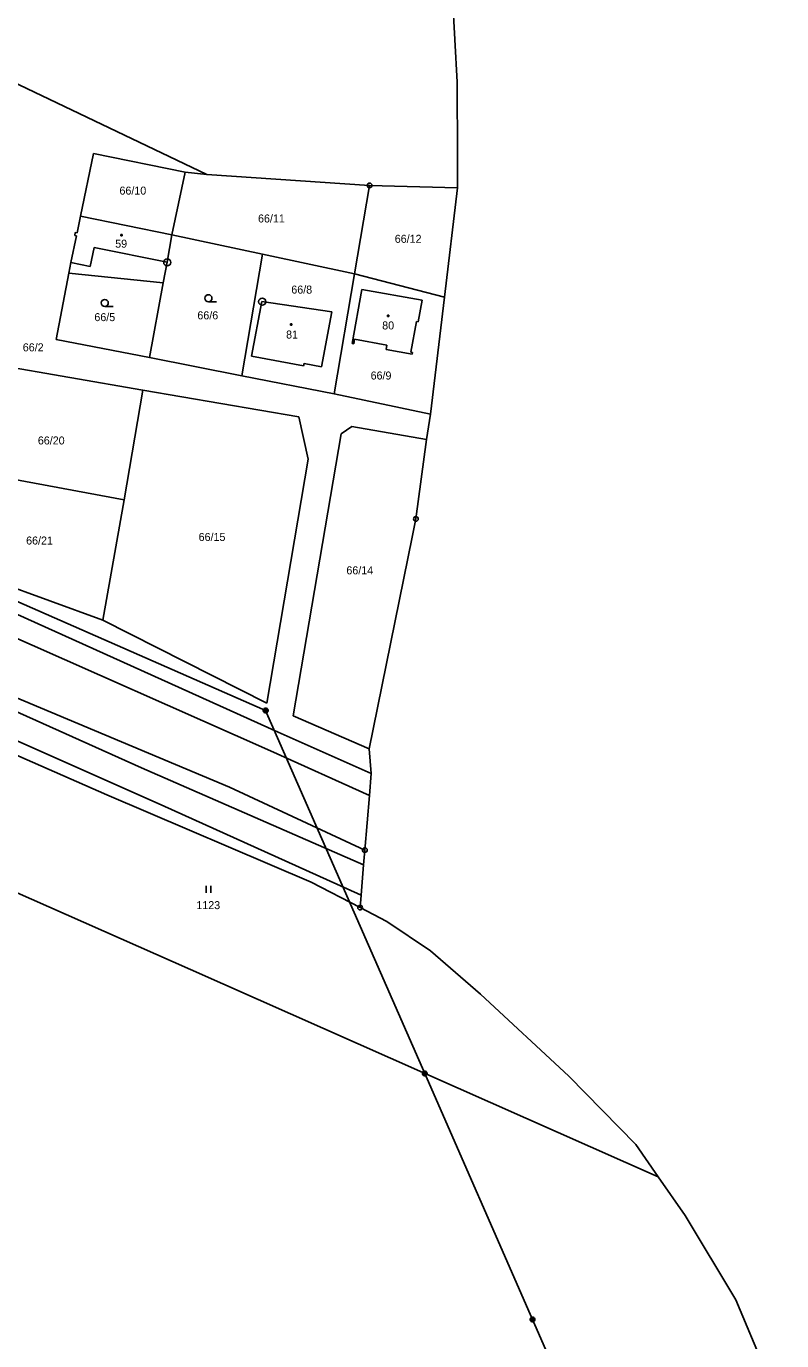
# Model space of a CAD drawing. Extents: x -796130 to -793145, y -1109506 to -1106267.
# Drawn here: x -794147 to -793986.5, y -1108157.6 to -1107878.4 of the extents above; entities that cross this region are included whole.
import ezdxf

# ---------------------------------------------------------------- set-up
doc = ezdxf.new("R2010")
doc.units = 0
for name, color, linetype in [('Vrstva 1', 7, 'Continuous'), ('Vrstva 12', 7, 'Continuous'), ('Vrstva 14', 7, 'Continuous'), ('Vrstva 15', 7, 'Continuous'), ('Vrstva 2', 7, 'Continuous'), ('Vrstva 23', 7, 'Continuous'), ('Vrstva 25', 7, 'Continuous'), ('Vrstva 26', 7, 'Continuous'), ('Vrstva 28', 7, 'Continuous'), ('Vrstva 4', 7, 'Continuous')]:
    doc.layers.add(name, color=color, linetype=linetype)

msp = doc.modelspace()

# ---------------------------------------------------------------- linework, layer by layer
at = {"layer": 'Vrstva 1'}
for p, q in [((-794175.87, -1107877.74), (-794108.67, -1107909.82)), ((-794132.74, -1107905.36), (-794135.47, -1107918.72)), ((-794113.29, -1107909.33), (-794132.74, -1107905.36)), ((-794116.06, -1107922.68), (-794113.29, -1107909.33)), ((-794108.67, -1107909.82), (-794113.29, -1107909.33)), ((-794108.67, -1107909.82), (-794074.07, -1107912.16)), ((-794077.27, -1107930.93), (-794074.07, -1107912.16)), ((-794074.07, -1107912.16), (-794055.42, -1107912.68)), ((-794136.2, -1107922.24), (-794135.47, -1107918.72)), ((-794135.47, -1107918.72), (-794116.06, -1107922.68)), ((-794137.52, -1107928.56), (-794136.34, -1107922.88)), ((-794136.73, -1107922.8), (-794136.63, -1107922.15)), ((-794136.34, -1107922.88), (-794136.73, -1107922.8)), ((-794136.63, -1107922.15), (-794136.2, -1107922.24)), ((-794116.06, -1107922.68), (-794117.11, -1107928.47)), ((-794116.06, -1107922.68), (-794096.83, -1107926.75)), ((-794137.96, -1107930.82), (-794137.52, -1107928.56)), ((-794117.11, -1107928.47), (-794117.92, -1107932.88)), ((-794096.83, -1107926.75), (-794101.21, -1107952.61)), ((-794077.27, -1107930.93), (-794096.83, -1107926.75)), ((-794140.69, -1107944.88), (-794137.96, -1107930.82)), ((-794117.92, -1107932.88), (-794137.96, -1107930.82)), ((-794077.27, -1107930.93), (-794081.59, -1107956.43)), ((-794077.27, -1107930.93), (-794058.17, -1107935.92)), ((-794117.92, -1107932.88), (-794120.84, -1107948.74)), ((-794077.81, -1107945.74), (-794075.75, -1107934.3)), ((-794075.75, -1107934.3), (-794062.94, -1107936.55)), ((-794099.19, -1107948.43), (-794097, -1107936.82)), ((-794097, -1107936.82), (-794082.08, -1107939.06)), ((-794062.94, -1107936.55), (-794063.78, -1107941.17)), ((-794082.08, -1107939.06), (-794084.29, -1107950.7)), ((-794064.14, -1107941.1), (-794065.34, -1107947.62)), ((-794063.78, -1107941.17), (-794064.14, -1107941.1)), ((-794140.69, -1107944.88), (-794120.84, -1107948.74)), ((-794077.46, -1107945.8), (-794077.81, -1107945.74)), ((-794077.28, -1107944.84), (-794077.46, -1107945.8)), ((-794070.42, -1107946.08), (-794077.28, -1107944.84)), ((-794088.14, -1107950.51), (-794099.19, -1107948.43)), ((-794070.59, -1107947.04), (-794070.42, -1107946.08)), ((-794065.02, -1107948.04), (-794070.59, -1107947.04)), ((-794065.34, -1107947.62), (-794064.96, -1107947.69)), ((-794064.96, -1107947.69), (-794065.02, -1107948.04)), ((-794153.9, -1107950.19), (-794122.25, -1107955.65)), ((-794120.84, -1107948.74), (-794101.21, -1107952.61)), ((-794088, -1107949.99), (-794088.14, -1107950.51)), ((-794084.29, -1107950.7), (-794088, -1107949.99)), ((-794101.21, -1107952.61), (-794081.59, -1107956.43)), ((-794122.25, -1107955.65), (-794126.24, -1107978.94)), ((-794122.25, -1107955.65), (-794089.09, -1107961.35)), ((-794081.59, -1107956.43), (-794061.11, -1107960.74)), ((-794089.09, -1107961.35), (-794087.14, -1107970.33)), ((-794090.35, -1108024.9), (-794080.1, -1107964.97)), ((-794080.1, -1107964.97), (-794077.82, -1107963.41)), ((-794077.82, -1107963.41), (-794061.96, -1107966.12)), ((-794087.14, -1107970.33), (-794095.89, -1108022.19)), ((-794158.08, -1107973.04), (-794126.24, -1107978.94)), ((-794126.24, -1107978.94), (-794130.79, -1108004.55)), ((-794130.79, -1108004.55), (-794161.9, -1107993.23)), ((-794168.15, -1107994.62), (-794093.53, -1108028.31)), ((-794169.94, -1107999.17), (-794095.11, -1108032.28)), ((-794095.89, -1108022.19), (-794130.79, -1108004.55)), ((-794158.82, -1108016.94), (-794103.82, -1108039.99)), ((-794129.88, -1108041.67), (-794165.82, -1108025.89)), ((-794074.16, -1108031.9), (-794090.35, -1108024.9)), ((-794093.53, -1108028.31), (-794073.75, -1108037.09)), ((-794095.11, -1108032.28), (-794074.13, -1108041.77)), ((-794103.82, -1108039.99), (-794075.09, -1108053.38)), ((-794196.39, -1108041.5), (-794112.13, -1108078.79)), ((-794086.5, -1108060.2), (-794129.88, -1108041.67)), ((-794076.1, -1108065.62), (-794086.5, -1108060.2)), ((-794112.13, -1108078.79), (-794012.75, -1108122.82))]:
    msp.add_line(p, q, dxfattribs=at)
at = {"layer": 'Vrstva 12'}
for p, q in [((-794096.16, -1108023.73), (-794162.66, -1107994.6)), ((-794062.37, -1108100.85), (-794096.16, -1108023.73)), ((-794039.45, -1108153.13), (-794062.37, -1108100.85)), ((-794018.04, -1108201.97), (-794039.45, -1108153.13))]:
    msp.add_line(p, q, dxfattribs=at)
at = {"layer": 'Vrstva 2'}
for p, q in [((-794132.62, -1107925.33), (-794133.44, -1107929.39)), ((-794117.11, -1107928.47), (-794132.62, -1107925.33)), ((-794133.44, -1107929.39), (-794137.52, -1107928.56)), ((-794122.52, -1108035.9), (-794180.45, -1108009.94)), ((-794181.93, -1108015.5), (-794118.39, -1108043.8)), ((-794075.35, -1108056.55), (-794122.52, -1108035.9)), ((-794118.39, -1108043.8), (-794075.88, -1108062.99))]:
    msp.add_line(p, q, dxfattribs=at)
at = {"layer": 'Vrstva 23'}
for p, q in [((-794108.32, -1107936.89), (-794106.57, -1107936.89)), ((-794130.34, -1107937.89), (-794128.59, -1107937.89)), ((-794108.81, -1108062.51), (-794108.81, -1108061.01)), ((-794107.81, -1108061.01), (-794107.81, -1108062.51))]:
    msp.add_line(p, q, dxfattribs=at)
for centre in [(-794130.34, -1107937.14), (-794108.32, -1107936.14)]:
    msp.add_circle(centre, 0.75, dxfattribs=at)
at = {"layer": 'Vrstva 25'}
for p, q in [((-794126.92, -1107922.61), (-794126.62, -1107922.61)), ((-794126.92, -1107922.91), (-794126.92, -1107922.61)), ((-794126.62, -1107922.91), (-794126.92, -1107922.91)), ((-794126.62, -1107922.61), (-794126.62, -1107922.91)), ((-794070.29, -1107939.74), (-794069.99, -1107939.74)), ((-794070.29, -1107940.04), (-794070.29, -1107939.74)), ((-794069.99, -1107940.04), (-794070.29, -1107940.04)), ((-794069.99, -1107939.74), (-794069.99, -1107940.04)), ((-794090.89, -1107941.56), (-794090.59, -1107941.56)), ((-794090.89, -1107941.86), (-794090.89, -1107941.56)), ((-794090.59, -1107941.86), (-794090.89, -1107941.86)), ((-794090.59, -1107941.56), (-794090.59, -1107941.86))]:
    msp.add_line(p, q, dxfattribs=at)
at = {"layer": 'Vrstva 26'}
for p, q in [((-794096.66, -1108023.63), (-794096.56, -1108023.43)), ((-794096.66, -1108023.83), (-794096.66, -1108023.63)), ((-794096.56, -1108024.03), (-794096.66, -1108023.83)), ((-794096.56, -1108023.43), (-794096.46, -1108023.33)), ((-794096.46, -1108024.13), (-794096.56, -1108024.03)), ((-794096.46, -1108023.33), (-794096.26, -1108023.23)), ((-794096.46, -1108023.53), (-794096.46, -1108023.93)), ((-794096.46, -1108023.93), (-794096.26, -1108024.03)), ((-794096.26, -1108024.23), (-794096.46, -1108024.13)), ((-794096.26, -1108023.23), (-794096.06, -1108023.23)), ((-794096.26, -1108024.03), (-794096.26, -1108023.43)), ((-794096.26, -1108023.43), (-794096.06, -1108023.43)), ((-794096.06, -1108023.23), (-794095.86, -1108023.33)), ((-794096.06, -1108023.43), (-794096.06, -1108024.03)), ((-794096.06, -1108024.03), (-794095.86, -1108023.93)), ((-794095.86, -1108024.13), (-794096.06, -1108024.23)), ((-794095.86, -1108023.33), (-794095.76, -1108023.43)), ((-794095.86, -1108023.93), (-794095.86, -1108023.53)), ((-794095.76, -1108024.03), (-794095.86, -1108024.13)), ((-794095.76, -1108023.43), (-794095.66, -1108023.63)), ((-794095.66, -1108023.83), (-794095.76, -1108024.03)), ((-794095.66, -1108023.63), (-794095.66, -1108023.83)), ((-794096.06, -1108024.23), (-794096.26, -1108024.23)), ((-794062.87, -1108100.75), (-794062.77, -1108100.55)), ((-794062.87, -1108100.95), (-794062.87, -1108100.75)), ((-794062.77, -1108101.15), (-794062.87, -1108100.95)), ((-794062.77, -1108100.55), (-794062.67, -1108100.45)), ((-794062.67, -1108101.25), (-794062.77, -1108101.15)), ((-794062.67, -1108100.45), (-794062.47, -1108100.35)), ((-794062.67, -1108100.65), (-794062.67, -1108101.05)), ((-794062.67, -1108101.05), (-794062.47, -1108101.15)), ((-794062.47, -1108101.35), (-794062.67, -1108101.25)), ((-794062.47, -1108100.35), (-794062.27, -1108100.35)), ((-794062.47, -1108101.15), (-794062.47, -1108100.55)), ((-794062.47, -1108100.55), (-794062.27, -1108100.55)), ((-794062.27, -1108101.35), (-794062.47, -1108101.35)), ((-794062.27, -1108100.35), (-794062.07, -1108100.45)), ((-794062.27, -1108100.55), (-794062.27, -1108101.15)), ((-794062.27, -1108101.15), (-794062.07, -1108101.05)), ((-794062.07, -1108101.25), (-794062.27, -1108101.35)), ((-794062.07, -1108100.45), (-794061.97, -1108100.55)), ((-794062.07, -1108101.05), (-794062.07, -1108100.65)), ((-794061.97, -1108101.15), (-794062.07, -1108101.25)), ((-794061.97, -1108100.55), (-794061.87, -1108100.75)), ((-794061.87, -1108100.95), (-794061.97, -1108101.15)), ((-794061.87, -1108100.75), (-794061.87, -1108100.95)), ((-794039.95, -1108153.03), (-794039.85, -1108152.83)), ((-794039.95, -1108153.23), (-794039.95, -1108153.03)), ((-794039.85, -1108153.43), (-794039.95, -1108153.23)), ((-794039.85, -1108152.83), (-794039.75, -1108152.73)), ((-794039.75, -1108153.53), (-794039.85, -1108153.43)), ((-794039.75, -1108152.73), (-794039.55, -1108152.63)), ((-794039.75, -1108152.93), (-794039.75, -1108153.33)), ((-794039.75, -1108153.33), (-794039.55, -1108153.43)), ((-794039.55, -1108153.63), (-794039.75, -1108153.53)), ((-794039.55, -1108152.63), (-794039.35, -1108152.63)), ((-794039.55, -1108153.43), (-794039.55, -1108152.83)), ((-794039.55, -1108152.83), (-794039.35, -1108152.83)), ((-794039.35, -1108153.63), (-794039.55, -1108153.63)), ((-794039.35, -1108152.63), (-794039.15, -1108152.73)), ((-794039.35, -1108152.83), (-794039.35, -1108153.43)), ((-794039.35, -1108153.43), (-794039.15, -1108153.33)), ((-794039.15, -1108153.53), (-794039.35, -1108153.63)), ((-794039.15, -1108152.73), (-794039.05, -1108152.83)), ((-794039.15, -1108153.33), (-794039.15, -1108152.93)), ((-794039.05, -1108153.43), (-794039.15, -1108153.53)), ((-794039.05, -1108152.83), (-794038.95, -1108153.03)), ((-794038.95, -1108153.23), (-794039.05, -1108153.43)), ((-794038.95, -1108153.03), (-794038.95, -1108153.23))]:
    msp.add_line(p, q, dxfattribs=at)
at = {"layer": 'Vrstva 28'}
for centre, radius in [((-794074.07, -1107912.16), 0.5), ((-794074.07, -1107912.16), 0.01), ((-794117.08, -1107928.52), 0.75), ((-794117.08, -1107928.52), 0.01), ((-794096.9, -1107936.87), 0.75), ((-794096.9, -1107936.87), 0.01), ((-794064.25, -1107983.03), 0.5), ((-794064.25, -1107983.03), 0.01), ((-794075.09, -1108053.38), 0.5), ((-794075.09, -1108053.38), 0.01), ((-794076.1, -1108065.62), 0.5), ((-794076.1, -1108065.62), 0.01)]:
    msp.add_circle(centre, radius, dxfattribs=at)
at = {"layer": 'Vrstva 4'}
for p, q in [((-794057, -1107862.86), (-794055.44, -1107890.22)), ((-794055.43, -1107906.09), (-794055.44, -1107890.22)), ((-794055.42, -1107912.68), (-794055.43, -1107906.09)), ((-794058.17, -1107935.92), (-794055.42, -1107912.68)), ((-794061.11, -1107960.74), (-794058.17, -1107935.92)), ((-794061.96, -1107966.12), (-794061.11, -1107960.74)), ((-794064.25, -1107983.03), (-794061.96, -1107966.12)), ((-794065.03, -1107986.9), (-794064.25, -1107983.03)), ((-794074.16, -1108031.9), (-794065.03, -1107986.9)), ((-794073.75, -1108037.09), (-794074.16, -1108031.9)), ((-794073.75, -1108037.09), (-794074.13, -1108041.77)), ((-794074.13, -1108041.77), (-794075.09, -1108053.38)), ((-794075.09, -1108053.38), (-794075.35, -1108056.55)), ((-794075.35, -1108056.55), (-794075.88, -1108062.99)), ((-794075.88, -1108062.99), (-794076.1, -1108065.62)), ((-794070.44, -1108068.57), (-794076.1, -1108065.62)), ((-794061.13, -1108074.83), (-794070.44, -1108068.57)), ((-794050.55, -1108084.01), (-794061.13, -1108074.83)), ((-794031.78, -1108101.43), (-794050.55, -1108084.01)), ((-794017.53, -1108115.93), (-794031.78, -1108101.43)), ((-794012.75, -1108122.82), (-794017.53, -1108115.93)), ((-794007.06, -1108131.03), (-794012.75, -1108122.82)), ((-793996.28, -1108148.98), (-794007.06, -1108131.03)), ((-793986.52, -1108172.19), (-793996.28, -1108148.98))]:
    msp.add_line(p, q, dxfattribs=at)

# ---------------------------------------------------------------- texts
at = {"layer": 'Vrstva 14'}
for s, p in [('66/10', (-794127.22, -1107914.12)), ('66/11', (-794097.78, -1107920.04)), ('66/12', (-794068.73, -1107924.36)), ('66/8', (-794090.71, -1107935.15)), ('66/5', (-794132.55, -1107941)), ('66/6', (-794110.67, -1107940.62)), ('66/2', (-794147.76, -1107947.42)), ('66/9', (-794073.86, -1107953.41)), ('66/20', (-794144.56, -1107967.21)), ('66/21', (-794147.05, -1107988.47)), ('66/15', (-794110.4, -1107987.71)), ('66/14', (-794079.01, -1107994.8)), ('1123', (-794110.883, -1108065.94))]:
    msp.add_text(s, height=1.7, dxfattribs=at).set_placement(p)
at = {"layer": 'Vrstva 15'}
for s, p in [('59', (-794128.13, -1107925.4)), ('81', (-794091.82, -1107944.7)), ('80', (-794071.4, -1107942.77))]:
    msp.add_text(s, height=1.7, dxfattribs=at).set_placement(p)

doc.saveas('drawing.dxf')
